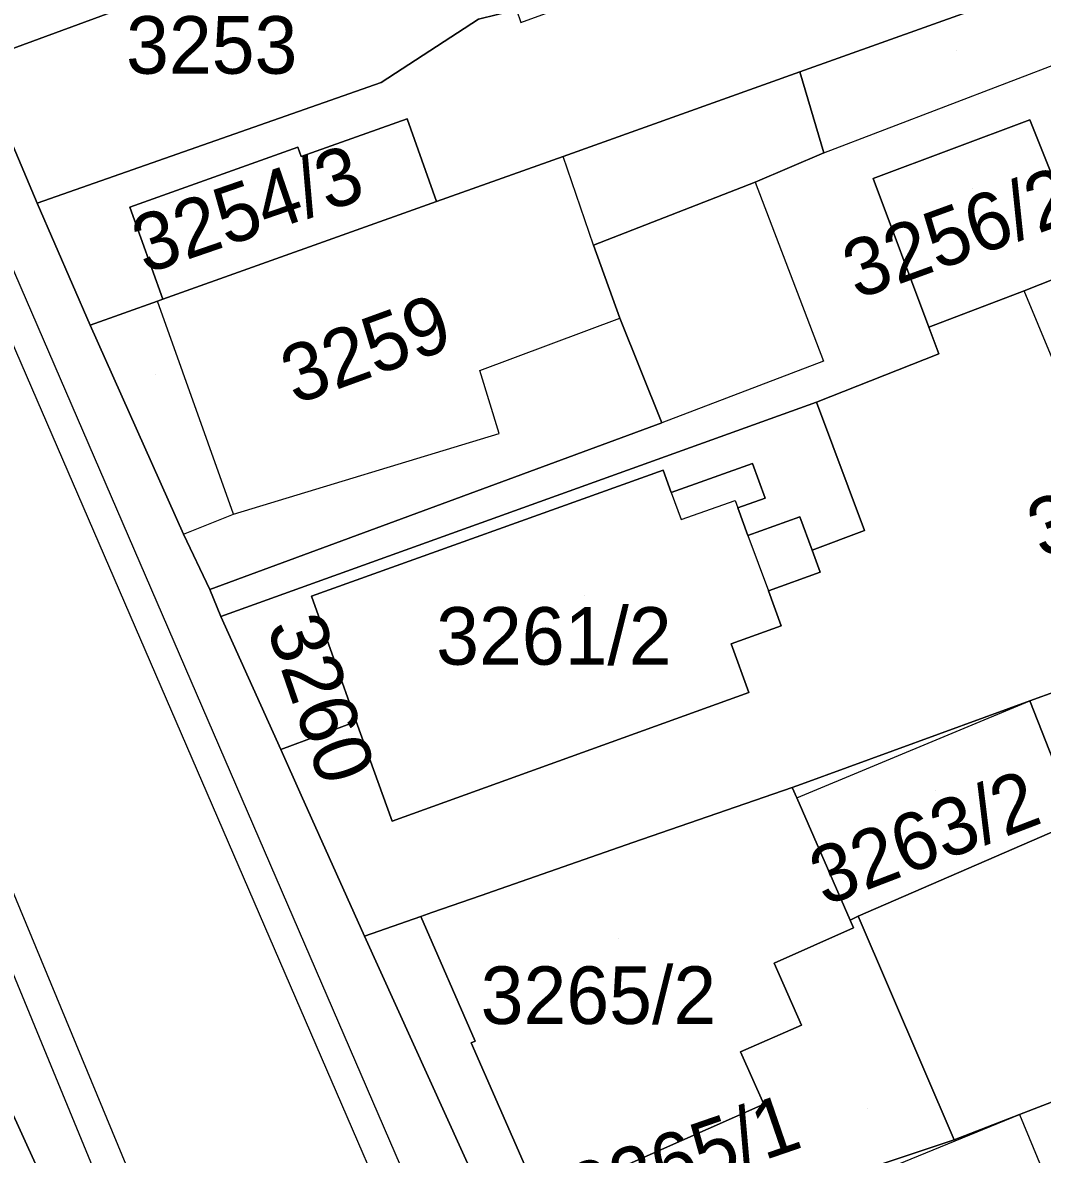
# Model space of a CAD drawing. Extents: x -262657 to -261595, y -1238015 to -1237156.
# Drawn here: x -261890.88 to -261855.46, y -1237853.34 to -1237814.02 of the extents above; entities that cross this region are included whole.
import ezdxf

# ---------------------------------------------------------------- set-up
doc = ezdxf.new("R2010")
doc.units = 0
for name, color, linetype in [('body_kn', 7, 'Continuous'), ('kladpar_druhypozemkov', 7, 'Continuous'), ('kladpar_hranice', 7, 'Continuous'), ('kladpar_parcelnecisla', 7, 'Continuous'), ('kladpar_plochy', 7, 'Continuous'), ('zappar_hrandruhpozemk', 7, 'Continuous')]:
    doc.layers.add(name, color=color, linetype=linetype)

msp = doc.modelspace()

# ---------------------------------------------------------------- linework, layer by layer
at = {"layer": 'body_kn'}
for p, q in [((-261863.88, -1237815.73), (-261863.88, -1237815.73)), ((-261878.43, -1237816.1), (-261878.43, -1237816.1)), ((-261877.52, -1237817.37), (-261877.52, -1237817.37)), ((-261855.9, -1237817.4), (-261855.9, -1237817.4)), ((-261881.32, -1237818.35), (-261881.32, -1237818.35)), ((-261863.05, -1237818.55), (-261863.05, -1237818.55)), ((-261863.05, -1237818.55), (-261863.05, -1237818.55)), ((-261881.2, -1237818.68), (-261881.2, -1237818.68)), ((-261872.11, -1237818.67), (-261872.11, -1237818.67)), ((-261865.43, -1237819.57), (-261865.43, -1237819.57)), ((-261865.43, -1237819.57), (-261865.43, -1237819.57)), ((-261861.34, -1237819.44), (-261861.34, -1237819.44)), ((-261890.38, -1237820.3), (-261890.38, -1237820.3)), ((-261890.38, -1237820.3), (-261890.38, -1237820.3)), ((-261887.16, -1237820.43), (-261887.16, -1237820.43)), ((-261876.5, -1237820.24), (-261876.5, -1237820.24)), ((-261871.05, -1237821.75), (-261871.05, -1237821.75)), ((-261871.05, -1237821.75), (-261871.05, -1237821.75)), ((-261886.2, -1237823.7), (-261886.2, -1237823.7)), ((-261886.01, -1237823.63), (-261886.01, -1237823.63)), ((-261886.01, -1237823.63), (-261886.01, -1237823.63)), ((-261856.09, -1237823.34), (-261856.09, -1237823.34)), ((-261870.14, -1237824.29), (-261870.14, -1237824.29)), ((-261888.53, -1237824.53), (-261888.53, -1237824.53)), ((-261888.53, -1237824.53), (-261888.53, -1237824.53)), ((-261859.4, -1237824.6), (-261859.4, -1237824.6)), ((-261859.4, -1237824.6), (-261859.4, -1237824.6)), ((-261859.06, -1237825.53), (-261859.06, -1237825.53)), ((-261863.06, -1237825.78), (-261863.06, -1237825.78)), ((-261875, -1237826.11), (-261875, -1237826.11)), ((-261863.31, -1237827.21), (-261863.31, -1237827.21)), ((-261868.68, -1237827.93), (-261868.68, -1237827.93)), ((-261874.33, -1237828.3), (-261874.33, -1237828.3)), ((-261868.63, -1237829.57), (-261868.63, -1237829.57)), ((-261865.53, -1237829.34), (-261865.53, -1237829.34)), ((-261868.35, -1237830.35), (-261868.35, -1237830.35)), ((-261868.35, -1237830.35), (-261868.35, -1237830.35)), ((-261866.13, -1237830.62), (-261866.13, -1237830.62)), ((-261865.09, -1237830.54), (-261865.09, -1237830.54)), ((-261883.55, -1237831.1), (-261883.55, -1237831.1)), ((-261866.04, -1237830.88), (-261866.04, -1237830.88)), ((-261863.88, -1237831.19), (-261863.88, -1237831.19)), ((-261868.01, -1237831.29), (-261868.01, -1237831.29)), ((-261885.29, -1237831.79), (-261885.29, -1237831.79)), ((-261885.29, -1237831.79), (-261885.29, -1237831.79)), ((-261865.69, -1237831.84), (-261865.69, -1237831.84)), ((-261865.69, -1237831.84), (-261865.69, -1237831.84)), ((-261861.64, -1237831.67), (-261861.64, -1237831.67)), ((-261863.46, -1237832.35), (-261863.46, -1237832.35)), ((-261863.18, -1237833.12), (-261863.18, -1237833.12)), ((-261884.38, -1237833.72), (-261884.38, -1237833.72)), ((-261884.38, -1237833.72), (-261884.38, -1237833.72)), ((-261880.85, -1237833.95), (-261880.85, -1237833.95)), ((-261864.97, -1237833.76), (-261864.97, -1237833.76)), ((-261884, -1237834.66), (-261884, -1237834.66)), ((-261884, -1237834.66), (-261884, -1237834.66)), ((-261864.53, -1237834.98), (-261864.53, -1237834.98)), ((-261866.27, -1237835.61), (-261866.27, -1237835.61)), ((-261865.66, -1237837.3), (-261865.66, -1237837.3)), ((-261855.9, -1237837.59), (-261855.9, -1237837.59)), ((-261879.29, -1237838.3), (-261879.29, -1237838.3)), ((-261881.91, -1237839.28), (-261881.91, -1237839.28)), ((-261881.91, -1237839.28), (-261881.91, -1237839.28)), ((-261864.15, -1237840.59), (-261864.15, -1237840.59)), ((-261863.83, -1237840.48), (-261863.83, -1237840.48)), ((-261881.21, -1237840.86), (-261881.21, -1237840.86)), ((-261863.99, -1237840.95), (-261863.99, -1237840.95)), ((-261863.99, -1237840.95), (-261863.99, -1237840.95)), ((-261878.04, -1237841.76), (-261878.04, -1237841.76)), ((-261878.04, -1237841.76), (-261878.04, -1237841.76)), ((-261869.68, -1237842.51), (-261869.68, -1237842.51)), ((-261874.95, -1237844.35), (-261874.95, -1237844.35)), ((-261874.53, -1237844.2), (-261874.53, -1237844.2)), ((-261876.67, -1237844.94), (-261876.67, -1237844.94)), ((-261877.05, -1237845.08), (-261877.05, -1237845.08)), ((-261862.14, -1237845.2), (-261862.14, -1237845.2)), ((-261861.86, -1237845.07), (-261861.86, -1237845.07)), ((-261862.02, -1237845.47), (-261862.02, -1237845.47)), ((-261879.01, -1237845.76), (-261879.01, -1237845.76)), ((-261864.78, -1237846.7), (-261864.78, -1237846.7)), ((-261863.83, -1237848.85), (-261863.83, -1237848.85)), ((-261875.3, -1237849.47), (-261875.3, -1237849.47)), ((-261875.16, -1237849.41), (-261875.16, -1237849.41)), ((-261865.95, -1237849.78), (-261865.95, -1237849.78)), ((-261865.14, -1237851.6), (-261865.14, -1237851.6)), ((-261856.26, -1237851.95), (-261856.26, -1237851.95)), ((-261858.52, -1237852.84), (-261858.52, -1237852.84))]:
    msp.add_line(p, q, dxfattribs=at)
at = {"layer": 'kladpar_druhypozemkov'}
for p, q in [((-261884.08, -1237814.08), (-261884.08, -1237814.08)), ((-261858.43, -1237815.01), (-261858.43, -1237815.01)), ((-261857.88, -1237819.77), (-261857.88, -1237819.77)), ((-261883.56, -1237819.82), (-261883.56, -1237819.82)), ((-261879.01, -1237824.4), (-261879.01, -1237824.4)), ((-261886.28, -1237826.25), (-261886.28, -1237826.25)), ((-261871.36, -1237833.93), (-261871.36, -1237833.93)), ((-261882.01, -1237835.54), (-261882.01, -1237835.54)), ((-261859.16, -1237840.69), (-261859.16, -1237840.69)), ((-261870.18, -1237845.83), (-261870.18, -1237845.83)), ((-261861.55, -1237851.74), (-261861.55, -1237851.74))]:
    msp.add_line(p, q, dxfattribs=at)
at = {"layer": 'kladpar_hranice'}
for points in [[(-261892.46, -1237815.38), (-261897.39, -1237804.1), (-261895.22, -1237803.36), (-261886.03, -1237800.22), (-261882.66, -1237799.08), (-261875.2, -1237796.53), (-261874.46, -1237799.37), (-261878.83, -1237801.48), (-261876.32, -1237809.44), (-261892.46, -1237815.38)], [(-261888.53, -1237824.53), (-261890.38, -1237820.3), (-261878.43, -1237816.1), (-261875.04, -1237813.91), (-261873.73, -1237813.58), (-261873.57, -1237814.02), (-261867.47, -1237811.78), (-261866.78, -1237813.65), (-261861.77, -1237811.81), (-261862.76, -1237809.14), (-261864.4, -1237809.74), (-261865.75, -1237806.08), (-261873.82, -1237809.05), (-261874, -1237808.64), (-261849.63, -1237800.16)], [(-261897.39, -1237804.1), (-261892.46, -1237815.38), (-261890.38, -1237820.3), (-261888.53, -1237824.53), (-261885.29, -1237831.79), (-261884.38, -1237833.72), (-261884, -1237834.66), (-261881.91, -1237839.28), (-261881.21, -1237840.86), (-261879.01, -1237845.76), (-261874.52, -1237855.64), (-261873.52, -1237857.83), (-261867.67, -1237871.68), (-261864.24, -1237879.6), (-261863.85, -1237880.67), (-261862.42, -1237883.92), (-261860.37, -1237888.77), (-261858.89, -1237892.19), (-261858.36, -1237893.51), (-261854.78, -1237901.75)], [(-261890.38, -1237820.3), (-261892.46, -1237815.38), (-261876.32, -1237809.44), (-261874, -1237808.64), (-261873.82, -1237809.05), (-261875.21, -1237809.56), (-261873.73, -1237813.58), (-261875.04, -1237813.91), (-261878.43, -1237816.1), (-261890.38, -1237820.3)], [(-261884, -1237834.66), (-261884.38, -1237833.72), (-261868.68, -1237827.93), (-261870.14, -1237824.29), (-261871.05, -1237821.75), (-261865.43, -1237819.57), (-261863.05, -1237818.55), (-261863.88, -1237815.73), (-261852.26, -1237811.58), (-261846.28, -1237809.35), (-261845.17, -1237808.98), (-261841.34, -1237817.73), (-261846.17, -1237819.71), (-261853.87, -1237822.46), (-261855.9, -1237817.4), (-261861.34, -1237819.44), (-261859.4, -1237824.6), (-261859.06, -1237825.53), (-261863.31, -1237827.21), (-261884, -1237834.66)], [(-261852.26, -1237811.58), (-261863.88, -1237815.73), (-261872.11, -1237818.67), (-261876.5, -1237820.24), (-261877.52, -1237817.37), (-261881.2, -1237818.68), (-261881.32, -1237818.35), (-261887.16, -1237820.43), (-261886.01, -1237823.63), (-261886.2, -1237823.7), (-261888.53, -1237824.53)], [(-261867.89, -1237908.17), (-261869.84, -1237903.85), (-261871.28, -1237900.38), (-261871.81, -1237899.1), (-261875.73, -1237889.62), (-261876.97, -1237886.62), (-261878.89, -1237882.22), (-261879.83, -1237879.78), (-261882.36, -1237872.9), (-261884.52, -1237867.46), (-261886.78, -1237861.7), (-261887.83, -1237859.39), (-261891.38, -1237851.58), (-261896.16, -1237839.29), (-261898.28, -1237834.11), (-261898.91, -1237832.53), (-261900.73, -1237828.11), (-261906.4, -1237814.7), (-261906.69, -1237814.03), (-261914.09, -1237816.76)], [(-261884.38, -1237833.72), (-261885.29, -1237831.79), (-261888.53, -1237824.53), (-261886.2, -1237823.7), (-261886.01, -1237823.63), (-261876.5, -1237820.24), (-261872.11, -1237818.67), (-261863.88, -1237815.73), (-261863.05, -1237818.55), (-261865.43, -1237819.57), (-261871.05, -1237821.75), (-261870.14, -1237824.29), (-261868.68, -1237827.93), (-261884.38, -1237833.72)], [(-261886.01, -1237823.63), (-261887.16, -1237820.43), (-261881.32, -1237818.35), (-261881.2, -1237818.68), (-261877.52, -1237817.37), (-261876.5, -1237820.24), (-261886.01, -1237823.63)], [(-261859.4, -1237824.6), (-261861.34, -1237819.44), (-261855.9, -1237817.4), (-261853.87, -1237822.46), (-261856.09, -1237823.34), (-261859.4, -1237824.6)], [(-261859.4, -1237824.6), (-261856.09, -1237823.34), (-261853.87, -1237822.46)], [(-261854.94, -1237837.24), (-261855.9, -1237837.59), (-261863.83, -1237840.48), (-261864.15, -1237840.59), (-261869.68, -1237842.51), (-261874.53, -1237844.2), (-261874.95, -1237844.35), (-261876.67, -1237844.94), (-261877.05, -1237845.08), (-261879.01, -1237845.76), (-261881.21, -1237840.86), (-261881.91, -1237839.28), (-261879.29, -1237838.3), (-261878.04, -1237841.76), (-261865.66, -1237837.3), (-261866.27, -1237835.61), (-261864.53, -1237834.98), (-261864.97, -1237833.76), (-261863.18, -1237833.12), (-261863.46, -1237832.35), (-261861.64, -1237831.67), (-261863.31, -1237827.21), (-261859.06, -1237825.53), (-261859.4, -1237824.6)], [(-261881.91, -1237839.28), (-261884, -1237834.66), (-261863.31, -1237827.21), (-261861.64, -1237831.67), (-261863.46, -1237832.35), (-261863.88, -1237831.19), (-261865.69, -1237831.84), (-261866.04, -1237830.88), (-261865.09, -1237830.54), (-261865.53, -1237829.34), (-261868.35, -1237830.35), (-261868.63, -1237829.57), (-261880.85, -1237833.95), (-261879.29, -1237838.3), (-261881.91, -1237839.28)], [(-261878.04, -1237841.76), (-261879.29, -1237838.3), (-261880.85, -1237833.95), (-261868.63, -1237829.57), (-261868.35, -1237830.35), (-261865.53, -1237829.34), (-261865.09, -1237830.54), (-261866.04, -1237830.88), (-261865.69, -1237831.84), (-261863.88, -1237831.19), (-261863.46, -1237832.35), (-261863.18, -1237833.12), (-261864.97, -1237833.76), (-261864.53, -1237834.98), (-261866.27, -1237835.61), (-261865.66, -1237837.3), (-261878.04, -1237841.76)], [(-261831.04, -1237842.68), (-261849.86, -1237849.49), (-261856.26, -1237851.95), (-261858.52, -1237852.84), (-261861.86, -1237845.07), (-261854.25, -1237841.77), (-261855.9, -1237837.59), (-261854.94, -1237837.24), (-261836.33, -1237829.97), (-261831.04, -1237842.68)], [(-261854.25, -1237841.77), (-261861.86, -1237845.07), (-261862.14, -1237845.2), (-261863.99, -1237840.95), (-261864.15, -1237840.59), (-261863.83, -1237840.48), (-261855.9, -1237837.59), (-261854.25, -1237841.77)], [(-261872.87, -1237855.02), (-261872.88, -1237854.99), (-261875.3, -1237849.47), (-261875.16, -1237849.41), (-261877.05, -1237845.08), (-261876.67, -1237844.94), (-261874.95, -1237844.35), (-261874.53, -1237844.2), (-261869.68, -1237842.51), (-261864.15, -1237840.59), (-261863.99, -1237840.95), (-261862.14, -1237845.2), (-261862.02, -1237845.47), (-261864.78, -1237846.7), (-261863.83, -1237848.85), (-261865.95, -1237849.78), (-261865.14, -1237851.6), (-261872.87, -1237855.02)], [(-261873.52, -1237857.83), (-261874.52, -1237855.64), (-261879.01, -1237845.76), (-261877.05, -1237845.08), (-261875.16, -1237849.41), (-261875.3, -1237849.47), (-261872.88, -1237854.99), (-261872.87, -1237855.02), (-261865.14, -1237851.6), (-261865.95, -1237849.78), (-261863.83, -1237848.85), (-261864.78, -1237846.7), (-261862.02, -1237845.47), (-261862.14, -1237845.2), (-261861.86, -1237845.07), (-261858.52, -1237852.84), (-261873.52, -1237857.83)], [(-261867.67, -1237871.68), (-261873.52, -1237857.83), (-261858.52, -1237852.84), (-261856.26, -1237851.95), (-261849.86, -1237849.49), (-261844.94, -1237862.93), (-261846.62, -1237863.53), (-261856.17, -1237866.91), (-261862.97, -1237869.61), (-261867.67, -1237871.68)], [(-261891.38, -1237851.58), (-261887.83, -1237859.39), (-261886.78, -1237861.7), (-261892.76, -1237864.26), (-261904.35, -1237869.07), (-261909.18, -1237857.27), (-261891.38, -1237851.58)]]:
    msp.add_lwpolyline(points, dxfattribs=at)
at = {"layer": 'kladpar_plochy'}
for points in [[(-261892.46, -1237815.38), (-261897.39, -1237804.1), (-261895.22, -1237803.36), (-261886.03, -1237800.22), (-261882.66, -1237799.08), (-261875.2, -1237796.53), (-261874.46, -1237799.37), (-261878.83, -1237801.48), (-261876.32, -1237809.44)], [(-261890.38, -1237820.3), (-261892.46, -1237815.38), (-261876.32, -1237809.44), (-261874, -1237808.64), (-261873.82, -1237809.05), (-261875.21, -1237809.56), (-261873.73, -1237813.58), (-261875.04, -1237813.91), (-261878.43, -1237816.1)], [(-261884, -1237834.66), (-261884.38, -1237833.72), (-261868.68, -1237827.93), (-261870.14, -1237824.29), (-261871.05, -1237821.75), (-261865.43, -1237819.57), (-261863.05, -1237818.55), (-261863.88, -1237815.73), (-261852.26, -1237811.58), (-261846.28, -1237809.35), (-261845.17, -1237808.98), (-261841.34, -1237817.73), (-261846.17, -1237819.71), (-261853.87, -1237822.46), (-261855.9, -1237817.4), (-261861.34, -1237819.44), (-261859.4, -1237824.6), (-261859.06, -1237825.53), (-261863.31, -1237827.21)], [(-261884.38, -1237833.72), (-261885.29, -1237831.79), (-261888.53, -1237824.53), (-261886.2, -1237823.7), (-261886.01, -1237823.63), (-261876.5, -1237820.24), (-261872.11, -1237818.67), (-261863.88, -1237815.73), (-261863.05, -1237818.55), (-261865.43, -1237819.57), (-261871.05, -1237821.75), (-261870.14, -1237824.29), (-261868.68, -1237827.93)], [(-261886.01, -1237823.63), (-261887.16, -1237820.43), (-261881.32, -1237818.35), (-261881.2, -1237818.68), (-261877.52, -1237817.37), (-261876.5, -1237820.24)], [(-261859.4, -1237824.6), (-261861.34, -1237819.44), (-261855.9, -1237817.4), (-261853.87, -1237822.46), (-261856.09, -1237823.34)], [(-261881.91, -1237839.28), (-261884, -1237834.66), (-261863.31, -1237827.21), (-261861.64, -1237831.67), (-261863.46, -1237832.35), (-261863.88, -1237831.19), (-261865.69, -1237831.84), (-261866.04, -1237830.88), (-261865.09, -1237830.54), (-261865.53, -1237829.34), (-261868.35, -1237830.35), (-261868.63, -1237829.57), (-261880.85, -1237833.95), (-261879.29, -1237838.3)], [(-261878.04, -1237841.76), (-261879.29, -1237838.3), (-261880.85, -1237833.95), (-261868.63, -1237829.57), (-261868.35, -1237830.35), (-261865.53, -1237829.34), (-261865.09, -1237830.54), (-261866.04, -1237830.88), (-261865.69, -1237831.84), (-261863.88, -1237831.19), (-261863.46, -1237832.35), (-261863.18, -1237833.12), (-261864.97, -1237833.76), (-261864.53, -1237834.98), (-261866.27, -1237835.61), (-261865.66, -1237837.3)], [(-261831.04, -1237842.68), (-261849.86, -1237849.49), (-261856.26, -1237851.95), (-261858.52, -1237852.84), (-261861.86, -1237845.07), (-261854.25, -1237841.77), (-261855.9, -1237837.59), (-261854.94, -1237837.24), (-261836.33, -1237829.97)], [(-261854.25, -1237841.77), (-261861.86, -1237845.07), (-261862.14, -1237845.2), (-261863.99, -1237840.95), (-261864.15, -1237840.59), (-261863.83, -1237840.48), (-261855.9, -1237837.59)], [(-261872.87, -1237855.02), (-261872.88, -1237854.99), (-261875.3, -1237849.47), (-261875.16, -1237849.41), (-261877.05, -1237845.08), (-261876.67, -1237844.94), (-261874.95, -1237844.35), (-261874.53, -1237844.2), (-261869.68, -1237842.51), (-261864.15, -1237840.59), (-261863.99, -1237840.95), (-261862.14, -1237845.2), (-261862.02, -1237845.47), (-261864.78, -1237846.7), (-261863.83, -1237848.85), (-261865.95, -1237849.78), (-261865.14, -1237851.6)], [(-261873.52, -1237857.83), (-261874.52, -1237855.64), (-261879.01, -1237845.76), (-261877.05, -1237845.08), (-261875.16, -1237849.41), (-261875.3, -1237849.47), (-261872.88, -1237854.99), (-261872.87, -1237855.02), (-261865.14, -1237851.6), (-261865.95, -1237849.78), (-261863.83, -1237848.85), (-261864.78, -1237846.7), (-261862.02, -1237845.47), (-261862.14, -1237845.2), (-261861.86, -1237845.07), (-261858.52, -1237852.84)], [(-261867.67, -1237871.68), (-261873.52, -1237857.83), (-261858.52, -1237852.84), (-261856.26, -1237851.95), (-261849.86, -1237849.49), (-261844.94, -1237862.93), (-261846.62, -1237863.53), (-261856.17, -1237866.91), (-261862.97, -1237869.61)], [(-261891.38, -1237851.58), (-261887.83, -1237859.39), (-261886.78, -1237861.7), (-261892.76, -1237864.26), (-261904.35, -1237869.07), (-261909.18, -1237857.27)]]:
    msp.add_lwpolyline(points, close=True, dxfattribs=at)
for points in [[(-261897.39, -1237804.1), (-261892.46, -1237815.38), (-261890.38, -1237820.3), (-261888.53, -1237824.53), (-261885.29, -1237831.79), (-261884.38, -1237833.72), (-261884, -1237834.66), (-261881.91, -1237839.28), (-261881.21, -1237840.86), (-261879.01, -1237845.76), (-261874.52, -1237855.64), (-261873.52, -1237857.83), (-261867.67, -1237871.68), (-261864.24, -1237879.6), (-261863.85, -1237880.67), (-261862.42, -1237883.92), (-261860.37, -1237888.77), (-261858.89, -1237892.19), (-261858.36, -1237893.51), (-261854.78, -1237901.75)], [(-261852.26, -1237811.58), (-261863.88, -1237815.73), (-261872.11, -1237818.67), (-261876.5, -1237820.24), (-261877.52, -1237817.37), (-261881.2, -1237818.68), (-261881.32, -1237818.35), (-261887.16, -1237820.43), (-261886.01, -1237823.63), (-261886.2, -1237823.7), (-261888.53, -1237824.53), (-261890.38, -1237820.3), (-261878.43, -1237816.1), (-261875.04, -1237813.91)], [(-261871.81, -1237899.1), (-261875.73, -1237889.62), (-261876.97, -1237886.62), (-261878.89, -1237882.22), (-261879.83, -1237879.78), (-261882.36, -1237872.9), (-261884.52, -1237867.46), (-261886.78, -1237861.7), (-261887.83, -1237859.39), (-261891.38, -1237851.58), (-261896.16, -1237839.29), (-261898.28, -1237834.11), (-261898.91, -1237832.53), (-261900.73, -1237828.11), (-261906.4, -1237814.7), (-261906.69, -1237814.03), (-261914.09, -1237816.76), (-261923.62, -1237819.21), (-261923.89, -1237818.34), (-261924, -1237817.96), (-261923.67, -1237817.87), (-261913.97, -1237813.57)], [(-261854.94, -1237837.24), (-261855.9, -1237837.59), (-261863.83, -1237840.48), (-261864.15, -1237840.59), (-261869.68, -1237842.51), (-261874.53, -1237844.2), (-261874.95, -1237844.35), (-261876.67, -1237844.94), (-261877.05, -1237845.08), (-261879.01, -1237845.76), (-261881.21, -1237840.86), (-261881.91, -1237839.28), (-261879.29, -1237838.3), (-261878.04, -1237841.76), (-261865.66, -1237837.3), (-261866.27, -1237835.61), (-261864.53, -1237834.98), (-261864.97, -1237833.76), (-261863.18, -1237833.12), (-261863.46, -1237832.35), (-261861.64, -1237831.67), (-261863.31, -1237827.21), (-261859.06, -1237825.53), (-261859.4, -1237824.6), (-261856.09, -1237823.34), (-261853.87, -1237822.46)]]:
    msp.add_lwpolyline(points, dxfattribs=at)
at = {"layer": 'zappar_hrandruhpozemk'}
for p, q in [((-261924.51, -1237745.6), (-261870.74, -1237869.97)), ((-261863.05, -1237818.55), (-261851.34, -1237814.07)), ((-261871.05, -1237821.75), (-261872.11, -1237818.67)), ((-261865.43, -1237819.57), (-261863.06, -1237825.78)), ((-261883.55, -1237831.1), (-261886.2, -1237823.7)), ((-261854.38, -1237827.48), (-261856.09, -1237823.34)), ((-261863.06, -1237825.78), (-261868.68, -1237827.93)), ((-261883.55, -1237831.1), (-261874.33, -1237828.3)), ((-261868.35, -1237830.35), (-261868.01, -1237831.29)), ((-261868.01, -1237831.29), (-261866.13, -1237830.62)), ((-261866.13, -1237830.62), (-261866.04, -1237830.88)), ((-261885.29, -1237831.79), (-261883.55, -1237831.1)), ((-261865.69, -1237831.84), (-261864.97, -1237833.76)), ((-261863.99, -1237840.95), (-261855.9, -1237837.59))]:
    msp.add_line(p, q, dxfattribs=at)
for points in [[(-261857.29, -1237903.53), (-261871.7, -1237870.32), (-261925.44, -1237746.09), (-261934.35, -1237714.96)], [(-261875, -1237886.44), (-261927.55, -1237758.77), (-261932.46, -1237746.83)], [(-261917.3, -1237781.31), (-261875.05, -1237883.26), (-261864.96, -1237906.9)], [(-261874.33, -1237828.3), (-261875, -1237826.11), (-261870.14, -1237824.29)], [(-261866.72, -1237856.24), (-261856.26, -1237851.95), (-261853.94, -1237857.55)]]:
    msp.add_lwpolyline(points, dxfattribs=at)

# ---------------------------------------------------------------- texts
at = {"layer": 'kladpar_parcelnecisla'}
for s, p in [('3253', (-261887.287, -1237815.8)), ('3261/2', (-261876.516, -1237836.33)), ('3265/2', (-261874.971, -1237848.81))]:
    msp.add_text(s, height=2, dxfattribs=at).set_placement(p)
for s, rotation, p in [('3254/3', 19, (-261886.618, -1237822.767)), ('3256/2', 20, (-261861.906, -1237823.652)), ('3259', 20, (-261881.42, -1237827.307)), ('3261/1', 20, (-261855.494, -1237832.653)), ('3260', 289, (-261882.42, -1237835.007)), ('3263/2', 21, (-261863.022, -1237844.727)), ('3265/1', 19, (-261871.454, -1237855.731))]:
    msp.add_text(s, height=2, rotation=rotation, dxfattribs=at).set_placement(p)

doc.saveas('drawing.dxf')
